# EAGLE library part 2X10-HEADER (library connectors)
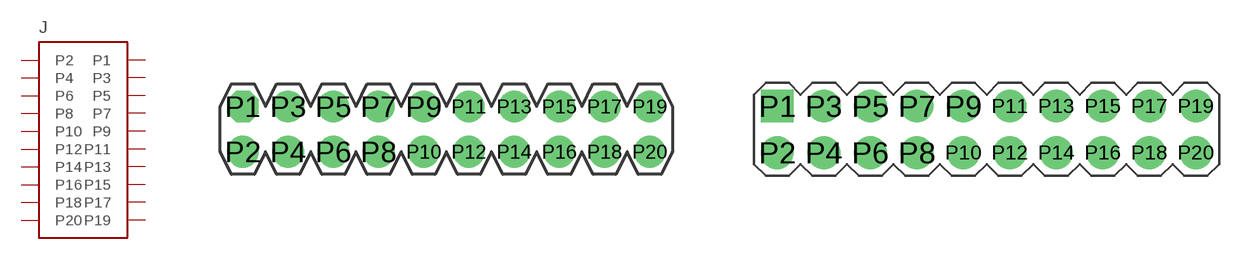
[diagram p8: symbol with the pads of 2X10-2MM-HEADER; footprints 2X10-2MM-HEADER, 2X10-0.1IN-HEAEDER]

Designator prefix J

## 2X10-HEADER2MM  [2X10-2MM-HEADER]
P1  P1  pas
P2  P2  pas
P3  P3  pas
P4  P4  pas
P5  P5  pas
P6  P6  pas
P7  P7  pas
P8  P8  pas
P9  P9  pas
P10  P10  pas
P11  P11  pas
P12  P12  pas
P13  P13  pas
P14  P14  pas
P15  P15  pas
P16  P16  pas
P17  P17  pas
P18  P18  pas
P19  P19  pas
P20  P20  pas

## 2X10-HEADER0.1IN  [2X10-0.1IN-HEAEDER]
Pads as for 2X10-2MM-HEADER

## Footprint 2X10-2MM-HEADER (pad centres in mm)
drill 0.85 pad 1.4 octagon: P1 -9,1
drill 0.85 pad 1.4 round: P2 -9,-1; P3 -7,1; P4 -7,-1; P5 -5,1; P6 -5,-1; P7 -3,1; P8 -3,-1; P9 -1,1; P10 -1,-1; P11 1,1; P12 1,-1; P13 3,1; P14 3,-1; P15 5,1; P16 5,-1; P17 7,1; P18 7,-1; P19 9,1; P20 9,-1

## Footprint 2X10-0.1IN-HEAEDER (pad centres in mm)
drill 1.05 pad 1.778 square: P1 -11.43,1.27
drill 1.05 pad 1.778 round: P2 -11.43,-1.27; P3 -8.89,1.27; P4 -8.89,-1.27; P5 -6.35,1.27; P6 -6.35,-1.27; P7 -3.81,1.27; P8 -3.81,-1.27; P9 -1.27,1.27; P10 -1.27,-1.27; P11 1.27,1.27; P12 1.27,-1.27; P13 3.81,1.27; P14 3.81,-1.27; P15 6.35,1.27; P16 6.35,-1.27; P17 8.89,1.27; P18 8.89,-1.27; P19 11.43,1.27; P20 11.43,-1.27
